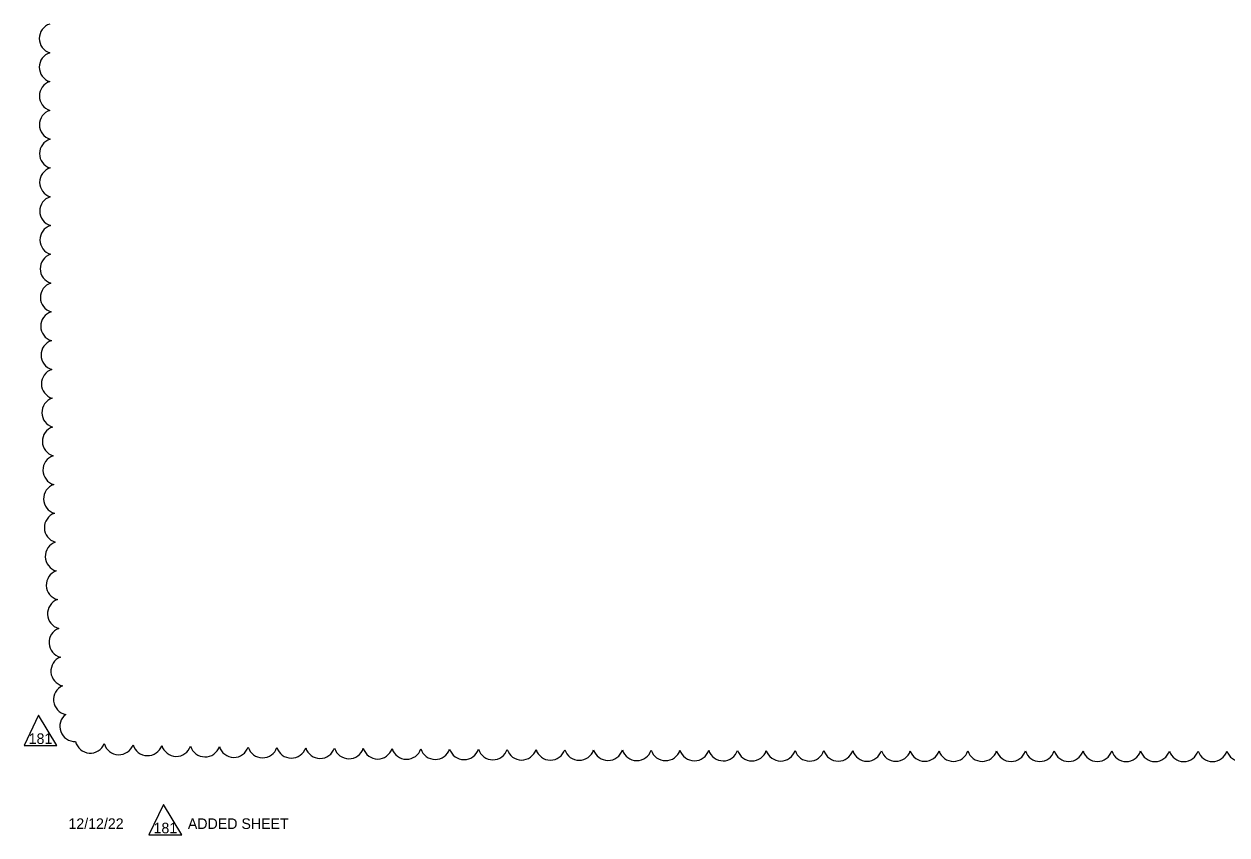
# Model space of a CAD drawing. Extents: x -811 to 10319, y -2309 to 9962.
# Drawn here: x -811.08 to -803.18, y -2257.92 to -2252.59 of the extents above; entities that cross this region are included whole.
import ezdxf

# ---------------------------------------------------------------- set-up
doc = ezdxf.new("R2010")
doc.units = 0
doc.layers.add('ScratchEle_dp', color=7, linetype='Continuous')

msp = doc.modelspace()

# ---------------------------------------------------------------- linework, layer by layer
at = {"layer": 'ScratchEle_dp'}
for points in [[(-810.9836, -2257.1301), (-811.0784, -2257.3308), (-810.8622, -2257.3308)], [(-810.1638, -2257.7169), (-810.2586, -2257.9175), (-810.0424, -2257.9175)]]:
    msp.add_lwpolyline(points, close=True, dxfattribs=at)
for centre, start, end in [((-810.8794, -2252.6874), 107.52584, 252.52584), ((-810.8792, -2252.8764), 107.56719, 252.56719), ((-810.8789, -2253.0654), 107.61129, 252.61129), ((-810.8785, -2253.2544), 107.65843, 252.65843), ((-810.8779, -2253.4434), 107.709, 252.709), ((-810.8771, -2253.6323), 107.76343, 252.76343), ((-810.8761, -2253.8213), 107.82224, 252.82224), ((-810.875, -2254.0103), 107.88605, 252.88605), ((-810.8736, -2254.1992), 107.95561, 252.95561), ((-810.8719, -2254.3882), 108.03183, 253.03183), ((-810.87, -2254.5771), 108.11586, 253.11586), ((-810.8679, -2254.7661), 108.20912, 253.20912), ((-810.8653, -2254.955), 108.31345, 253.31345), ((-810.8625, -2255.1439), 108.43121, 253.43121), ((-810.8592, -2255.3328), 108.56556, 253.56556), ((-810.8554, -2255.5217), 108.72081, 253.72081), ((-810.8511, -2255.7105), 108.903, 253.903), ((-810.8461, -2255.8994), 109.12096, 254.12096), ((-810.8403, -2256.0881), 109.38818, 254.38818), ((-810.8335, -2256.2768), 109.72657, 254.72657), ((-810.8255, -2256.4654), 110.17469, 255.17469), ((-810.8156, -2256.6538), 110.80877, 255.80877), ((-810.8031, -2256.8419), 111.80931, 256.80931), ((-810.7858, -2257.029), 113.77584, 258.77584), ((-810.7447, -2257.2049), 127.48462, 272.48462), ((-810.644, -2257.2813), 193.17348, 338.17348), ((-810.4565, -2257.2918), 195.39639, 340.39639), ((-810.2679, -2257.2978), 195.97806, 340.97806), ((-810.0791, -2257.3023), 196.28744, 341.28744), ((-809.8902, -2257.306), 196.48754, 341.48754), ((-809.7013, -2257.3091), 196.63065, 341.63065), ((-809.5124, -2257.3118), 196.73959, 341.73959), ((-809.3235, -2257.3141), 196.8261, 341.8261), ((-809.1345, -2257.3162), 196.89697, 341.89697), ((-808.9455, -2257.3181), 196.95641, 341.95641), ((-808.7566, -2257.3198), 197.0072, 342.0072), ((-808.5676, -2257.3214), 197.05125, 342.05125), ((-808.3786, -2257.3228), 197.08993, 342.08993), ((-808.1897, -2257.3241), 197.12425, 342.12425), ((-808.0007, -2257.3253), 197.15498, 342.15498), ((-807.8117, -2257.3264), 197.18269, 342.18269), ((-807.6227, -2257.3274), 197.20786, 342.20786), ((-807.4337, -2257.3283), 197.23085, 342.23085), ((-807.2447, -2257.3292), 197.25195, 342.25195), ((-807.0557, -2257.3299), 197.27142, 342.27142), ((-806.8668, -2257.3307), 197.28945, 342.28945), ((-806.6778, -2257.3313), 197.30621, 342.30621), ((-806.4888, -2257.332), 197.32184, 342.32184), ((-806.2998, -2257.3325), 197.33647, 342.33647), ((-806.1108, -2257.333), 197.3502, 342.3502), ((-805.9218, -2257.3335), 197.36311, 342.36311), ((-805.7328, -2257.3339), 197.37529, 342.37529), ((-805.5438, -2257.3343), 197.3868, 342.3868), ((-805.3548, -2257.3347), 197.3977, 342.3977), ((-805.1658, -2257.335), 197.40804, 342.40804), ((-804.9768, -2257.3353), 197.41787, 342.41787), ((-804.7878, -2257.3355), 197.42723, 342.42723), ((-804.5988, -2257.3358), 197.43616, 342.43616), ((-804.4098, -2257.336), 197.44468, 342.44468), ((-804.2208, -2257.3361), 197.45283, 342.45283), ((-804.0318, -2257.3363), 197.46064, 342.46064), ((-803.8428, -2257.3364), 197.46812, 342.46812), ((-803.6538, -2257.3365), 197.4753, 342.4753), ((-803.4649, -2257.3366), 197.4822, 342.4822), ((-803.2759, -2257.3366), 197.48884, 342.48884), ((-803.0869, -2257.3366), 197.49523, 342.49523)]:
    msp.add_arc(centre, 0.0991, start, end, dxfattribs=at)

# ---------------------------------------------------------------- texts
for s, p in [('181', (-811.0481, -2257.3201)), ('12/12/22', (-810.7871, -2257.8783)), ('181', (-810.2282, -2257.9068)), ('ADDED SHEET', (-810.003, -2257.8783))]:
    msp.add_text(s, height=0.0696, dxfattribs=at).set_placement(p)

doc.saveas('drawing.dxf')
